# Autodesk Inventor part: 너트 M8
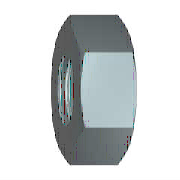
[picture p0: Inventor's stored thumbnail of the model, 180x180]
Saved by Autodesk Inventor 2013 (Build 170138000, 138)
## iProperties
IsCustomPart: 1
Created: 2012-02
Part Number: 너트 M8
Material: 강철, 연강
Description: 6각 너트
Document SubType Name: Modeling
Standard: KS B 1012
Designer: mduedu
Standards Organization: KS
Language: ko-KR
Size Designation: M8
Categories: <MemberInstance><Categories><Category DisplayName="조임쇠" InternalName="e4da775c-781d-43d5-af7c-5136215cf5a6" Mnemonic="FSTN"><Category DisplayName="너트" InternalN
Density: 1 g/cm^3
Author: mduedu
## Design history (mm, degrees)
sketch "스케치1"
  geometry: L1 (-7.506, 0)-(-3.753, 6.5); L2 (-3.753, 6.5)-(3.753, 6.5); L3 (3.753, 6.5)-(7.506, 0); L4 (7.506, 0)-(3.753, -6.5); L5 (3.753, -6.5)-(-3.753, -6.5); L6 (-3.753, -6.5)-(-7.506, 0); 2 further points
  constraints: 12 end point, 1 coincident, 1 horizontal, 11 other
  dimensions: "d0" = 15.01111 distance of L3.end L1.start (= 1.1547 x SW)
extrude "본체" new body sketch "스케치1" distance "d1" = 5 (= KOH); taper "d2" = 0 deg
sketch "스케치2"
  geometry: L1 (0, 3.753)-(0, 7.506) reference; L2 (0, 7.506)-(5, 7.506) reference; L3 (5, 3.753)-(5, 7.506) reference; L4 (-1, 0)-(6, 0) reference; L5 (0.581, 7.506)-(0, 6.5); L6 (4.419, 7.506)-(5, 6.5)
  constraints: 4 end point, 4 point on line
  dimensions: "d3" = 30 deg angle of L1 L5 (= ANG1); "d4" = 30 deg angle of L3 L6 (= ANG2); "d5" = 13 diameter of L5.end L4 (= SW0); "d6" = 13 diameter of L6.end L4 (= SW01)
revolve "모따기1" sketch "스케치2" stored, may be unused: angle "d7" = 90 deg
sketch "스케치3"
  geometry: A1 r 6.5 centre (0, 0) between (-3.25, -5.629) and (3.25, -5.629) reference; 1 further point
  constraints: 1 coincident
hole "스레드" sketch "스케치3" at (0, 0) diameter "d25" = 6.647; stored, may be unused: countersink angle "d29" = 82 deg, drill point angle "d31" = 118 deg; dims "d26" = 6, "d27" = 4, "d28" = 2, "d30" = 8
workaxis "Work Axis1"
workplane "Work Plane1"
body "Solid1"
chamfer "모따기2" distance "d8" = 0.67658 (= -0.5 x GD1 + 0.5 x NND); stored, may be unused: angle "d9" = 30 deg, second distance "d40" = 0.67658 (= -0.5 x GD1 + 0.5 x NND)
chamfer "모따기3" distance "d10" = 0.67658 (= -0.5 x GD1 + 0.5 x NND); stored, may be unused: angle "d11" = 30 deg, second distance "d41" = 0.67658 (= -0.5 x GD1 + 0.5 x NND)
other parameters: "ANG1" = 30 deg [user parameter; used in 1 equation term], "ANG2" = 30 deg [user parameter; used in 1 equation term], "NND" = 8 [user parameter; used in 4 equation terms], "KOH" = 5 [user parameter; used in 1 equation term], "SW" = 13 [user parameter; used in 4 equation terms], "SW0" = 13 (= SW) [user parameter; used in 1 equation term], "SW01" = 13 (= SW) [user parameter; used in 1 equation term], "GD1" = 6.64684 (computed from THREADDIA, PTC, TOA) [user parameter; used in 4 equation terms], "d13" = 0, "d14" = 0, "d39" = 0, "d42" = 0, "GUL" = 0.67658 (= 0.541266 x PTC) [user parameter], "TPU" = 8 (computed from PTC) [user parameter], "THREADDIA" = 8 [user parameter; used in 1 equation term], "TOA" = 30 deg [user parameter; used in 1 equation term], "PTC" = 1.25 [user parameter; used in 4 equation terms], "E0" = 15.015 (= 1.155 x SW) [user parameter], "GAL" = 0.67658 (= 0.541266 x PTC) [user parameter]
